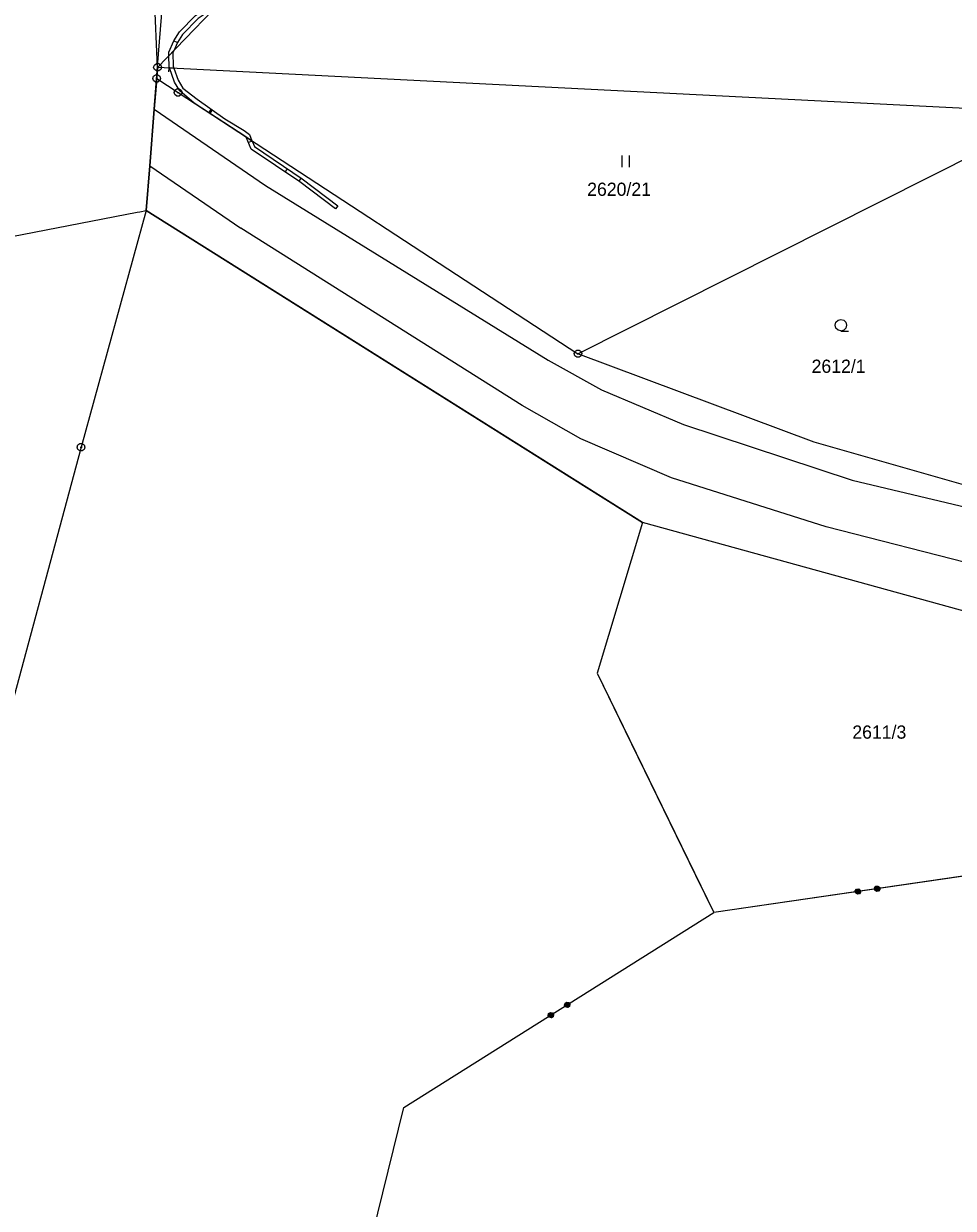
# Model space of a CAD drawing. Extents: x -760611 to -758411, y -1176479 to -1174807.
# Drawn here: x -759476.2 to -759356.6, y -1175903.8 to -1175751.3 of the extents above; entities that cross this region are included whole.
import ezdxf

# ---------------------------------------------------------------- set-up
doc = ezdxf.new("R2010")
doc.units = 0
for name, color, linetype in [('1', 7, 'Continuous'), ('11', 7, 'Continuous'), ('13', 7, 'Continuous'), ('2', 7, 'Continuous'), ('3', 7, 'Continuous'), ('4', 7, 'Continuous'), ('8', 7, 'Continuous')]:
    doc.layers.add(name, color=color, linetype=linetype)

msp = doc.modelspace()

# ---------------------------------------------------------------- linework, layer by layer
at = {"layer": '1'}
for p, q in [((-759458.99, -1175756.9), (-759461.64, -1175694.85)), ((-759458.99, -1175756.9), (-759451.87, -1175749.56)), ((-759458.99, -1175756.9), (-759459.11, -1175758.33)), ((-759354.15, -1175762.26), (-759458.99, -1175756.9)), ((-759459.11, -1175758.33), (-759459.43, -1175762.28)), ((-759459.11, -1175758.33), (-759456.35, -1175760.13)), ((-759456.35, -1175760.13), (-759404.88, -1175793.76)), ((-759459.43, -1175762.28), (-759460.01, -1175769.57)), ((-759404.88, -1175793.76), (-759347.02, -1175764.62)), ((-759460.01, -1175769.57), (-759460.47, -1175775.32)), ((-759460.47, -1175775.32), (-759468.84, -1175805.79)), ((-759396.59, -1175815.47), (-759460.47, -1175775.32)), ((-759374.48, -1175805.16), (-759404.88, -1175793.76)), ((-759468.84, -1175805.79), (-759483.74, -1175861.06)), ((-759338.73, -1175815.39), (-759374.48, -1175805.16)), ((-759396.59, -1175815.47), (-759402.42, -1175834.88)), ((-759341.91, -1175830.54), (-759396.59, -1175815.47)), ((-759402.42, -1175834.88), (-759387.4, -1175865.69)), ((-759347.71, -1175859.9), (-759387.4, -1175865.69)), ((-759427.31, -1175890.79), (-759387.4, -1175865.69)), ((-759439.7, -1175941.1), (-759427.31, -1175890.79))]:
    msp.add_line(p, q, dxfattribs=at)
for points in [[(-759366.45, -1175862.96), (-759366.67, -1175862.8), (-759366.7, -1175862.53), (-759366.54, -1175862.31), (-759366.28, -1175862.28), (-759366.06, -1175862.44), (-759366.02, -1175862.7), (-759366.18, -1175862.92), (-759366.45, -1175862.96), (-759366.45, -1175862.92), (-759366.21, -1175862.88), (-759366.14, -1175862.79), (-759366.54, -1175862.85), (-759366.63, -1175862.78), (-759366.07, -1175862.7), (-759366.08, -1175862.62), (-759366.64, -1175862.7), (-759366.65, -1175862.62), (-759366.1, -1175862.54), (-759366.11, -1175862.46), (-759366.66, -1175862.54), (-759366.59, -1175862.45), (-759366.2, -1175862.4), (-759366.29, -1175862.33), (-759366.53, -1175862.36)], [(-759368.92, -1175863.32), (-759369.14, -1175863.16), (-759369.18, -1175862.89), (-759369.02, -1175862.67), (-759368.75, -1175862.64), (-759368.54, -1175862.8), (-759368.5, -1175863.06), (-759368.66, -1175863.28), (-759368.92, -1175863.32), (-759368.9, -1175863.27), (-759368.66, -1175863.24), (-759368.59, -1175863.15), (-759368.99, -1175863.21), (-759369.08, -1175863.14), (-759368.53, -1175863.06), (-759368.54, -1175862.98), (-759369.09, -1175863.06), (-759369.1, -1175862.98), (-759368.55, -1175862.9), (-759368.56, -1175862.82), (-759369.12, -1175862.9), (-759369.05, -1175862.81), (-759368.65, -1175862.75), (-759368.74, -1175862.68), (-759368.98, -1175862.72)], [(-759406.31, -1175877.21), (-759406.05, -1175877.27), (-759405.91, -1175877.5), (-759405.97, -1175877.76), (-759406.2, -1175877.9), (-759406.46, -1175877.84), (-759406.6, -1175877.61), (-759406.54, -1175877.35), (-759406.31, -1175877.21), (-759406.32, -1175877.26), (-759406.52, -1175877.39), (-759406.55, -1175877.5), (-759406.21, -1175877.28), (-759406.1, -1175877.31), (-759406.57, -1175877.61), (-759406.53, -1175877.67), (-759406.06, -1175877.38), (-759406.01, -1175877.44), (-759406.49, -1175877.74), (-759406.44, -1175877.81), (-759405.97, -1175877.51), (-759406, -1175877.62), (-759406.33, -1175877.83), (-759406.22, -1175877.86), (-759406.02, -1175877.73)], [(-759408.43, -1175878.54), (-759408.17, -1175878.6), (-759408.03, -1175878.83), (-759408.09, -1175879.09), (-759408.31, -1175879.23), (-759408.58, -1175879.17), (-759408.72, -1175878.94), (-759408.66, -1175878.68), (-759408.43, -1175878.54), (-759408.42, -1175878.58), (-759408.62, -1175878.71), (-759408.65, -1175878.82), (-759408.31, -1175878.6), (-759408.2, -1175878.63), (-759408.67, -1175878.93), (-759408.63, -1175878.99), (-759408.16, -1175878.7), (-759408.11, -1175878.76), (-759408.59, -1175879.06), (-759408.54, -1175879.13), (-759408.07, -1175878.83), (-759408.1, -1175878.94), (-759408.43, -1175879.15), (-759408.32, -1175879.18), (-759408.12, -1175879.05)]]:
    msp.add_lwpolyline(points, dxfattribs=at)
at = {"layer": '11'}
msp.add_line((-759460.47, -1175775.32), (-759406, -1175809.55), dxfattribs=at)
for points in [[(-759460.47, -1175775.32), (-759460.01, -1175769.57), (-759459.43, -1175762.28), (-759458.99, -1175756.79), (-759457.81, -1175741.95), (-759456.01, -1175714.03)], [(-759502.75, -1175783.52), (-759461.61, -1175775.54), (-759461.29, -1175775.48), (-759460.47, -1175775.32)], [(-759406, -1175809.55), (-759396.59, -1175815.47), (-759402.42, -1175834.88), (-759398.81, -1175842.28), (-759389.74, -1175860.89), (-759387.4, -1175865.69)], [(-759184.2, -1175898.4), (-759211.78, -1175887.63), (-759233.27, -1175879.23), (-759246.54, -1175874.04), (-759277.8, -1175867.68), (-759281.99, -1175867.21), (-759291.26, -1175866.18), (-759295.49, -1175865.71), (-759312.63, -1175848.51), (-759323.52, -1175839.9), (-759341.91, -1175860.23), (-759347.71, -1175859.9), (-759387.4, -1175865.69)]]:
    msp.add_lwpolyline(points, dxfattribs=at)
at = {"layer": '13'}
for p, q in [((-759456.45, -1175753.72), (-759456.91, -1175753.52)), ((-759457.56, -1175756.97), (-759457.59, -1175757.47)), ((-759452.11, -1175762.27), (-759452.4, -1175762.68)), ((-759452.24, -1175762.83), (-759451.96, -1175762.41)), ((-759446.85, -1175766.34), (-759447.63, -1175765.83)), ((-759446.83, -1175766.38), (-759447.29, -1175766.58)), ((-759442.56, -1175770.38), (-759442.28, -1175769.96)), ((-759440.53, -1175771.13), (-759440.83, -1175771.53))]:
    msp.add_line(p, q, dxfattribs=at)
for points in [[(-759457.53, -1175755.4), (-759457.54, -1175754.95), (-759456.89, -1175753.49), (-759456.18, -1175752.34), (-759454.1, -1175750.22), (-759452.38, -1175749.08), (-759451.87, -1175748.79), (-759451.87, -1175749.37), (-759452.11, -1175749.51), (-759453.78, -1175750.6), (-759455.78, -1175752.66), (-759456.45, -1175753.71), (-759456.91, -1175754.76)], [(-759457.01, -1175756.75), (-759456.92, -1175757.01), (-759457.46, -1175756.98), (-759457.51, -1175756.85), (-759457.53, -1175755.4), (-759456.91, -1175754.76), (-759457.04, -1175755.05)], [(-759436.11, -1175775.11), (-759440.68, -1175771.64), (-759446.93, -1175767.43), (-759447.61, -1175765.88), (-759447.63, -1175765.83), (-759446.85, -1175766.34), (-759446.82, -1175766.4), (-759446.53, -1175767.09), (-759440.38, -1175771.24), (-759435.81, -1175774.71)]]:
    msp.add_lwpolyline(points, close=True, dxfattribs=at)
msp.add_lwpolyline([(-759447.63, -1175765.83), (-759454.27, -1175761.5), (-759456.11, -1175759.92), (-759456.8, -1175758.79), (-759457.46, -1175756.98), (-759456.92, -1175757.01), (-759456.34, -1175758.57), (-759455.73, -1175759.58), (-759453.92, -1175761), (-759450.33, -1175763.53), (-759447.83, -1175765.01), (-759447.18, -1175765.56), (-759446.85, -1175766.34)], dxfattribs=at)
at = {"layer": '3'}
for p, q in [((-759399.25, -1175768.26), (-759399.25, -1175769.76)), ((-759398.25, -1175769.76), (-759398.25, -1175768.26))]:
    msp.add_line(p, q, dxfattribs=at)
msp.add_lwpolyline([(-759371.03, -1175790.82), (-759371.41, -1175790.72), (-759371.68, -1175790.45), (-759371.78, -1175790.08), (-759371.68, -1175789.71), (-759371.41, -1175789.44), (-759371.04, -1175789.34), (-759370.67, -1175789.44), (-759370.4, -1175789.71), (-759370.3, -1175790.09), (-759370.4, -1175790.47), (-759370.67, -1175790.74), (-759371.05, -1175790.84), (-759370.05, -1175790.84)], dxfattribs=at)
at = {"layer": '4'}
for p, q in [((-759459.43, -1175762.28), (-759445.11, -1175772.1)), ((-759460.01, -1175769.57), (-759448.28, -1175777.6)), ((-759445.11, -1175772.1), (-759408.73, -1175794.58)), ((-759412.05, -1175800.42), (-759448.28, -1175777.6)), ((-759408.73, -1175794.58), (-759401.85, -1175798.39)), ((-759401.85, -1175798.39), (-759391.31, -1175802.85)), ((-759404.52, -1175804.71), (-759412.05, -1175800.42)), ((-759391.31, -1175802.85), (-759369.59, -1175810.05)), ((-759392.85, -1175809.74), (-759404.52, -1175804.71)), ((-759372.92, -1175816.06), (-759392.85, -1175809.74)), ((-759369.59, -1175810.05), (-759352.16, -1175814.16)), ((-759352.73, -1175821.21), (-759372.92, -1175816.06))]:
    msp.add_line(p, q, dxfattribs=at)
at = {"layer": '8'}
for p, q in [((-759459.11, -1175756.9), (-759458.87, -1175756.9)), ((-759459.23, -1175758.33), (-759458.99, -1175758.33)), ((-759456.47, -1175760.13), (-759456.23, -1175760.13)), ((-759405, -1175793.76), (-759404.76, -1175793.76)), ((-759468.96, -1175805.79), (-759468.72, -1175805.79))]:
    msp.add_line(p, q, dxfattribs=at)
for points in [[(-759458.84, -1175756.42), (-759458.59, -1175756.6), (-759458.49, -1175756.89), (-759458.59, -1175757.18), (-759458.84, -1175757.36), (-759459.15, -1175757.36), (-759459.4, -1175757.18), (-759459.5, -1175756.89), (-759459.4, -1175756.6), (-759459.15, -1175756.42)], [(-759458.96, -1175757.85), (-759458.71, -1175758.03), (-759458.61, -1175758.32), (-759458.71, -1175758.61), (-759458.96, -1175758.79), (-759459.27, -1175758.79), (-759459.52, -1175758.61), (-759459.62, -1175758.32), (-759459.52, -1175758.03), (-759459.27, -1175757.85)], [(-759456.2, -1175759.65), (-759455.95, -1175759.83), (-759455.85, -1175760.12), (-759455.95, -1175760.41), (-759456.2, -1175760.59), (-759456.51, -1175760.59), (-759456.76, -1175760.41), (-759456.86, -1175760.12), (-759456.76, -1175759.83), (-759456.51, -1175759.65)], [(-759404.73, -1175793.28), (-759404.48, -1175793.46), (-759404.38, -1175793.75), (-759404.48, -1175794.04), (-759404.73, -1175794.22), (-759405.04, -1175794.22), (-759405.29, -1175794.04), (-759405.39, -1175793.75), (-759405.29, -1175793.46), (-759405.04, -1175793.28)], [(-759468.69, -1175805.31), (-759468.44, -1175805.49), (-759468.34, -1175805.78), (-759468.44, -1175806.07), (-759468.69, -1175806.25), (-759469, -1175806.25), (-759469.25, -1175806.07), (-759469.35, -1175805.78), (-759469.25, -1175805.49), (-759469, -1175805.31)]]:
    msp.add_lwpolyline(points, close=True, dxfattribs=at)

# ---------------------------------------------------------------- texts
at = {"layer": '2'}
for s, p in [('2620/21', (-759403.7, -1175773.44)), ('2612/1', (-759374.81, -1175796.22)), ('2611/3', (-759369.57, -1175843.31))]:
    msp.add_text(s, height=1.7, dxfattribs=at).set_placement(p)

doc.saveas('drawing.dxf')
